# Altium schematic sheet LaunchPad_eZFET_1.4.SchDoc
size 431 x 279 mm; Date: Not shown in title block; ApprovedBy: Not shown in title block; CheckedBy: Not shown in title block; Author: Not shown in title block; CompanyName: Not shown in title block; Engineer: Not shown in title block; Organization: Not shown in title block; Address1: Not shown in title block; Address2: Not shown in title block; Address3: Not shown in title block; Address4: Not shown in title block; DocumentNumber: 1; Revision: Use project parameter SCH_Rev; SheetNumber: 1; SheetTotal: 3; PageSetup: Record=PageOptions¦CenterHorizontal=True¦CenterVertical=True¦PrintScale=1.00¦XCorrection=1.00¦YCorrection=1.00¦PrintKind=0¦BorderSize=5000000¦LeftOffset=0¦BottomOffset=0¦Orientation=2¦PaperLength=1000¦PaperWidth=1000¦Scale=100¦PaperSource=15¦PrintQuality=600¦MediaType=1¦DitherType=10¦PaperKind=Letter¦PrintScaleMode=1
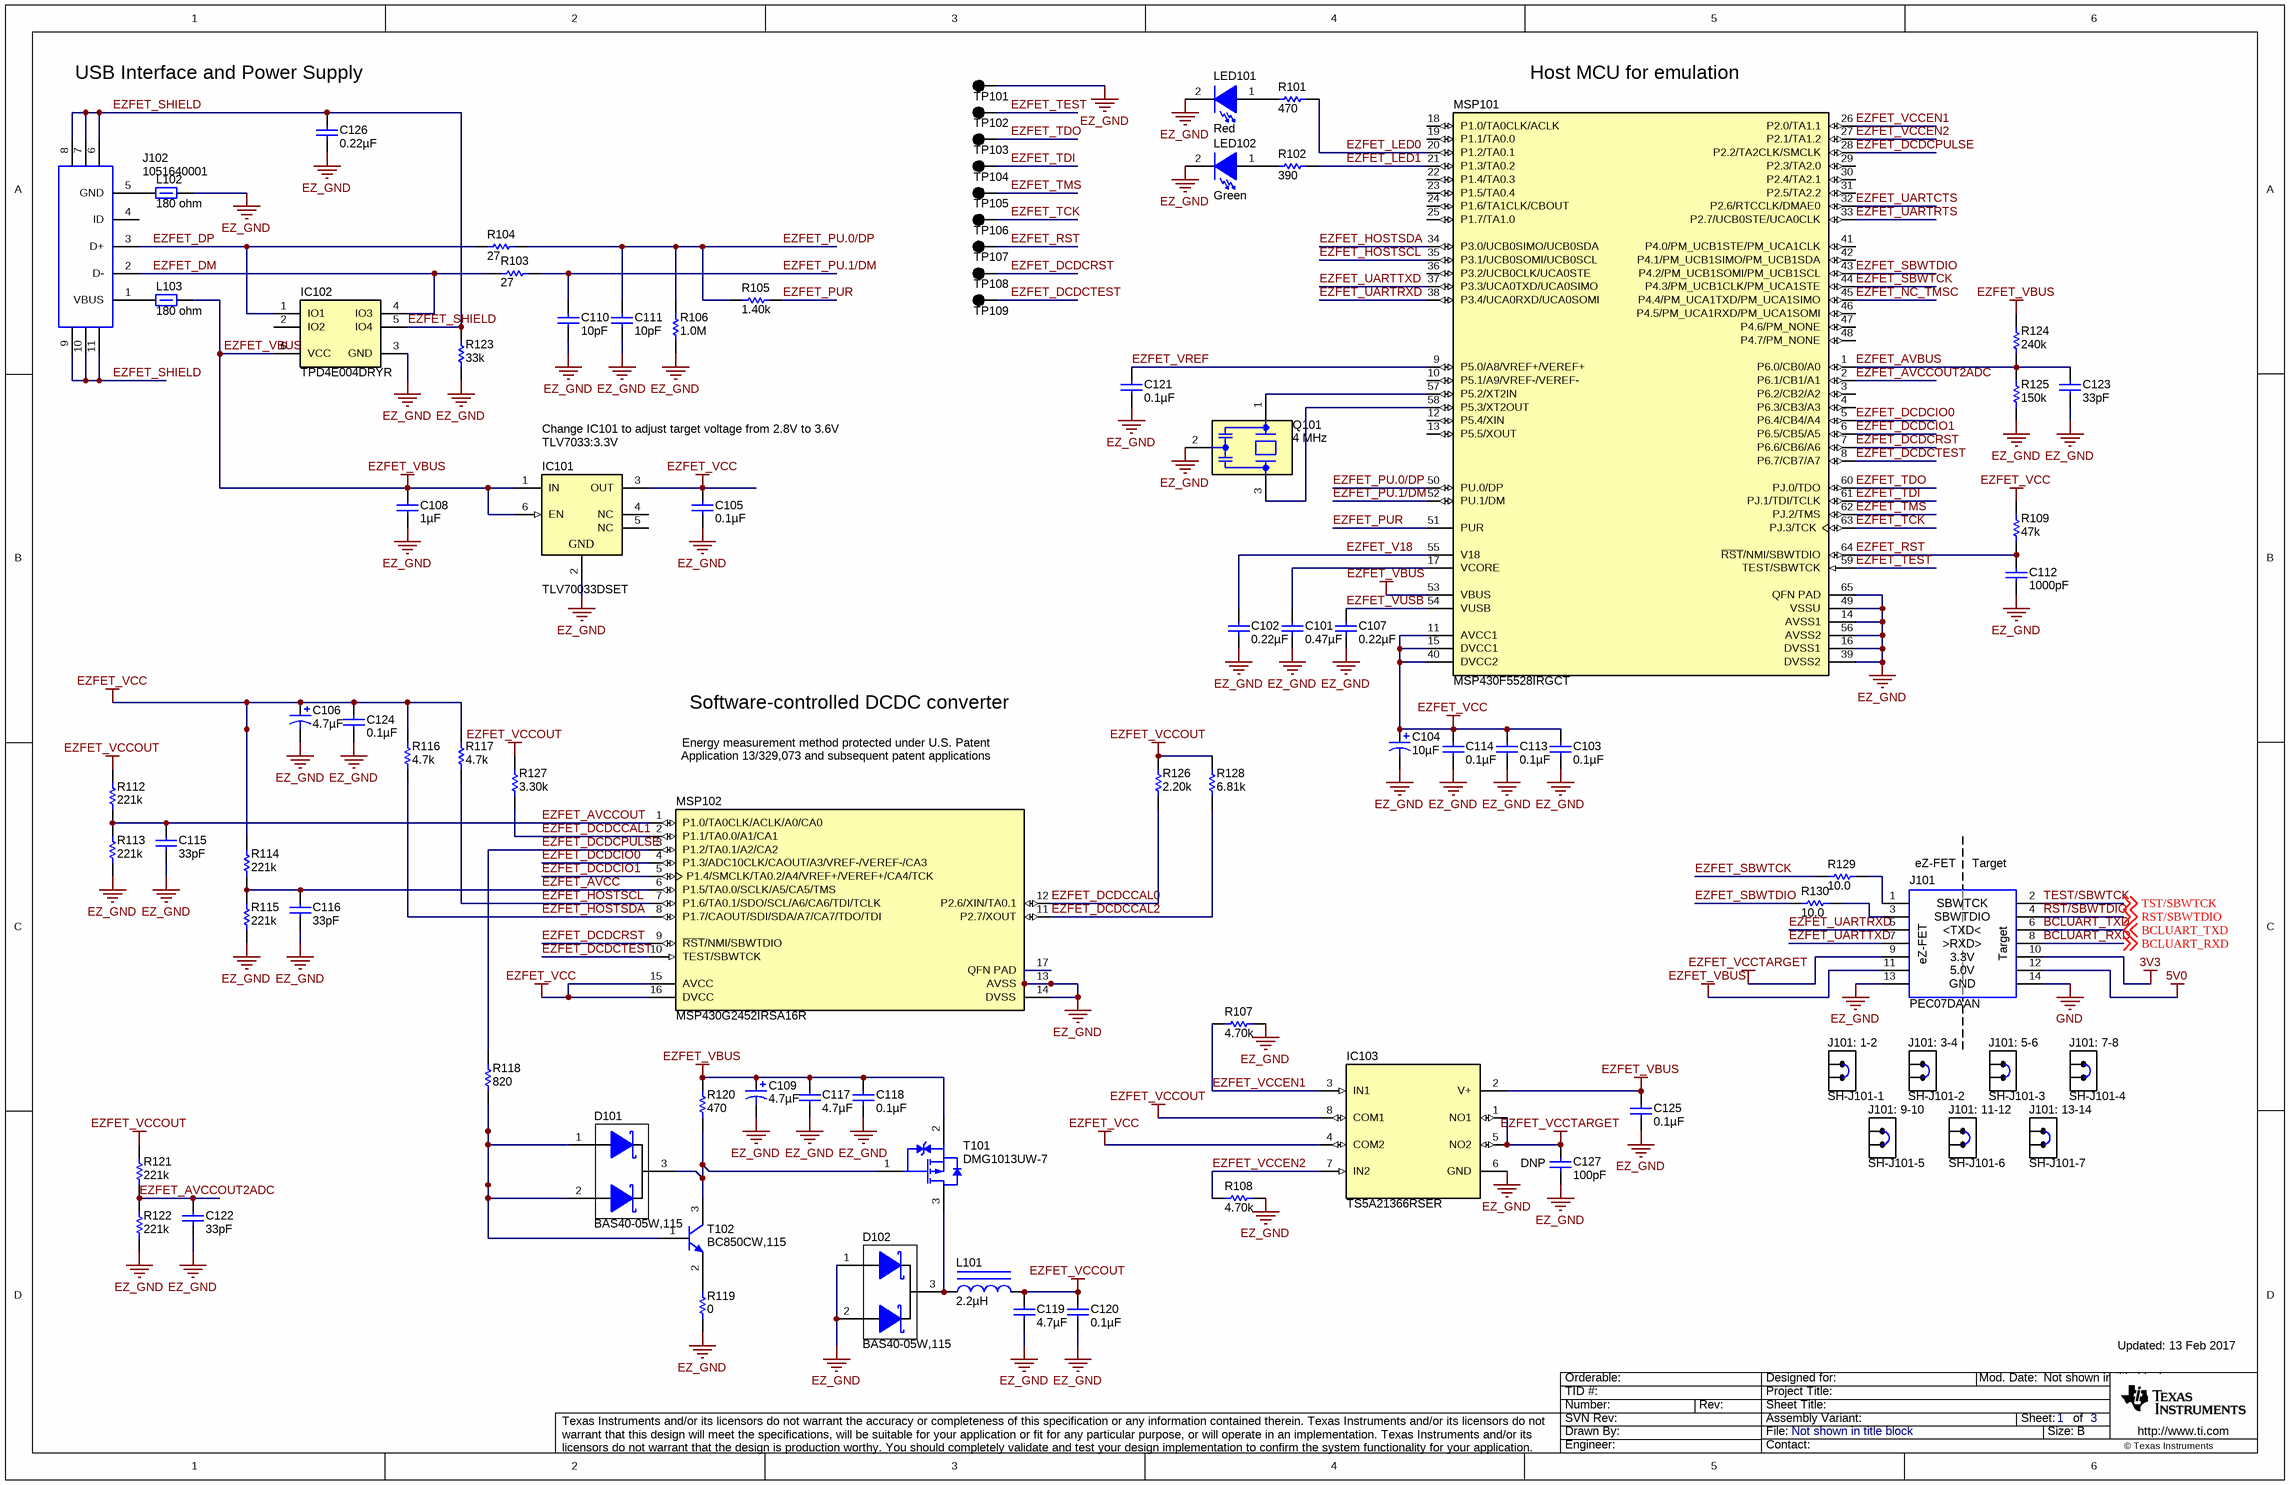
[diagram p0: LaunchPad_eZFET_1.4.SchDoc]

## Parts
C101  ValueDisplayed: 0.47µF  [0402]  (hidden comment: GRM155R61C474KE01)
C102  ValueDisplayed: 0.22µF  [0603]  (hidden comment: GRM188R61C224KA88D)
C103  ValueDisplayed: 0.1µF  [0402]  (hidden comment: GRM155R61A104KA01D)
C104  ValueDisplayed: 10µF  [3216-18]  (hidden comment: 293D106X0010A2TE3)
C105  ValueDisplayed: 0.1µF  [0402]  (hidden comment: GRM155R61A104KA01D)
C106  ValueDisplayed: 4.7µF  [3216-18]  (hidden comment: 293D475X9010A2TE3)
C107  ValueDisplayed: 0.22µF  [0603]  (hidden comment: GRM188R61C224KA88D)
C108  ValueDisplayed: 1µF  [0603]  (hidden comment: GRM185R61A105KE36D)
C109  ValueDisplayed: 4.7µF  [3216-18]  (hidden comment: 293D475X9010A2TE3)
C110  ValueDisplayed: 10pF  [0402]  (hidden comment: GRM1555C1H100JA01D)
C111  ValueDisplayed: 10pF  [0402]  (hidden comment: GRM1555C1H100JA01D)
C112  ValueDisplayed: 1000pF  [0402]  (hidden comment: GRM155R71H102KA01D)
C113  ValueDisplayed: 0.1µF  [0402]  (hidden comment: GRM155R61A104KA01D)
C114  ValueDisplayed: 0.1µF  [0402]  (hidden comment: GRM155R61A104KA01D)
C115  ValueDisplayed: 33pF  [0402]  (hidden comment: GRM1555C1H330JA01D)
C116  ValueDisplayed: 33pF  [0402]  (hidden comment: GRM1555C1H330JA01D)
C117  ValueDisplayed: 4.7µF  [0603]  (hidden comment: GRM188R61C475KAAJ)
C118  ValueDisplayed: 0.1µF  [0402]  (hidden comment: GRM155R61A104KA01D)
C119  ValueDisplayed: 4.7µF  [0603]  (hidden comment: GRM188R61C475KAAJ)
C120  ValueDisplayed: 0.1µF  [0402]  (hidden comment: GRM155R61A104KA01D)
C121  ValueDisplayed: 0.1µF  [0402]  (hidden comment: GRM155R61A104KA01D)
C122  ValueDisplayed: 33pF  [0402]  (hidden comment: GRM1555C1H330JA01D)
C123  ValueDisplayed: 33pF  [0402]  (hidden comment: GRM1555C1H330JA01D)
C124  ValueDisplayed: 0.1µF  [0402]  (hidden comment: GRM155R61A104KA01D)
C125  ValueDisplayed: 0.1µF  [0402]  (hidden comment: GRM155R61A104KA01D)
C126  ValueDisplayed: 0.22µF  [0402]  (hidden comment: GRM155R61A224KE19D)
C127  ValueDisplayed: 100pF  Note: DNP  [0402]  (hidden comment: GRM1555C1H101JA01D)
D101  BAS40-05W,115  [SOT-323]
D102  BAS40-05W,115  [SOT-323]
IC101  TLV70033DSET  [DSE0006A]
IC102  TPD4E004DRYR  [DRY0006A]
IC103  TS5A21366RSER  [RSE0008A]
J101  PEC07DAAN  [PEC07DAAN_Launchpad_EZ-FET]
J102  1051640001  [Molex_1051640001]
L101  ValueDisplayed: 2.2µH  [CBC2518]  (hidden comment: CBC2518T2R2M)
L102  ValueDisplayed: 180 ohm  [0603]  (hidden comment: 742792622)
L103  ValueDisplayed: 180 ohm  [0603]  (hidden comment: 742792622)
LED101  value Red  [LED_LTST-C190_Red]  (hidden comment: LTST-C190CKT)
LED102  value Green  [LED_LTST-C190]  (hidden comment: LTST-C190GKT)
MSP101  MSP430F5528IRGCT  [RGC0064B]
MSP102  MSP430G2452IRSA16R  [RSA0016B]
Q101  Frequency: 4 MHz  [Murata_CSTCR]  (hidden comment: CSTCR4M00G15L99-R0)
R101  ValueDisplayed: 470  [0402]  (hidden comment: CRCW0402470RJNED)
R102  ValueDisplayed: 390  [0402]  (hidden comment: CRCW0402390RJNED)
R103  ValueDisplayed: 27  [0402]  (hidden comment: CRCW040227R0JNED)
R104  ValueDisplayed: 27  [0402]  (hidden comment: CRCW040227R0JNED)
R105  ValueDisplayed: 1.40k  [0402]  (hidden comment: CRCW04021K40FKED)
R106  ValueDisplayed: 1.0M  [0402]  (hidden comment: CRCW04021M00JNED)
R107  ValueDisplayed: 4.70k  [0402]  (hidden comment: CRG0402F4K7)
R108  ValueDisplayed: 4.70k  [0402]  (hidden comment: CRG0402F4K7)
R109  ValueDisplayed: 47k  [0402]  (hidden comment: CRCW040247K0JNED)
R112  ValueDisplayed: 221k  [0402]  (hidden comment: CRCW0402221KFKED)
R113  ValueDisplayed: 221k  [0402]  (hidden comment: CRCW0402221KFKED)
R114  ValueDisplayed: 221k  [0402]  (hidden comment: CRCW0402221KFKED)
R115  ValueDisplayed: 221k  [0402]  (hidden comment: CRCW0402221KFKED)
R116  ValueDisplayed: 4.7k  [0402]  (hidden comment: CRCW04024K70JNED)
R117  ValueDisplayed: 4.7k  [0402]  (hidden comment: CRCW04024K70JNED)
R118  ValueDisplayed: 820  [0402]  (hidden comment: RC0402FR-07820RL)
R119  ValueDisplayed: 0  [0402]  (hidden comment: CRCW04020000Z0ED)
R120  ValueDisplayed: 470  [0402]  (hidden comment: CRCW0402470RJNED)
R121  ValueDisplayed: 221k  [0402]  (hidden comment: CRCW0402221KFKED)
R122  ValueDisplayed: 221k  [0402]  (hidden comment: CRCW0402221KFKED)
R123  ValueDisplayed: 33k  [0402]  (hidden comment: CRCW040233K0JNED)
R124  ValueDisplayed: 240k  [0402]  (hidden comment: CRCW0402240KFKED)
R125  ValueDisplayed: 150k  [0402]  (hidden comment: CRCW0402150KFKED)
R126  ValueDisplayed: 2.20k  [0402]  (hidden comment: CRCW04022K20FKED)
R127  ValueDisplayed: 3.30k  [0402]  (hidden comment: ERJ-2RKF3301X)
R128  ValueDisplayed: 6.81k  [0402]  (hidden comment: CRCW04026K81FKED)
R129  ValueDisplayed: 10.0  [0402]  (hidden comment: CRCW040210R0FKED)
R130  ValueDisplayed: 10.0  [0402]  (hidden comment: CRCW040210R0FKED)
SH-J101-1  Note: J101: 1-2  [SNT-100-BK-G]  (hidden comment: SNT-100-BK-G)
SH-J101-2  Note: J101: 3-4  [SNT-100-BK-G]  (hidden comment: SNT-100-BK-G)
SH-J101-3  Note: J101: 5-6  [SNT-100-BK-G]  (hidden comment: SNT-100-BK-G)
SH-J101-4  Note: J101: 7-8  [SNT-100-BK-G]  (hidden comment: SNT-100-BK-G)
SH-J101-5  Note: J101: 9-10  [SNT-100-BK-G]  (hidden comment: SNT-100-BK-G)
SH-J101-6  Note: J101: 11-12  [SNT-100-BK-G]  (hidden comment: SNT-100-BK-G)
SH-J101-7  Note: J101: 13-14  [SNT-100-BK-G]  (hidden comment: SNT-100-BK-G)
T101  DMG1013UW-7  [SOT-323]
T102  BC850CW,115  [SOT-323]
TP101  5001  [Keystone5001]  (value not drawn)
TP102  5001  [Keystone5001]  (value not drawn)
TP103  5001  [Keystone5001]  (value not drawn)
TP104  5001  [Keystone5001]  (value not drawn)
TP105  5001  [Keystone5001]  (value not drawn)
TP106  5001  [Keystone5001]  (value not drawn)
TP107  5001  [Keystone5001]  (value not drawn)
TP108  5001  [Keystone5001]  (value not drawn)
TP109  5001  [Keystone5001]  (value not drawn)

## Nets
3V3: J101.10
5V0: J101.12
EZ_GND: C101.1 C102.1 C103.1 C104.2(-) C105.1 C106.2(-) C107.1 C108.1 C109.2(-) C110.2 C111.2 C112.1 C113.1 C114.1 C115.1 C116.1 C117.1 C118.1 C119.1 C120.1 C121.1 C122.1 C123.1 C124.1 C125.1 C126.1 C127.2 D102.1(A) D102.2(A) IC101.2(GND) IC102.3(GND) IC103.6(GND) J101.13 L102.2 LED101.2(K) LED102.2(K) MSP101.14(AVSS1) MSP101.16(DVSS1) MSP101.39(DVSS2) MSP101.49(VSSU) MSP101.56(AVSS2) MSP101.65(QFN_PAD) MSP102.13(AVSS) MSP102.14(DVSS) MSP102.17(QFN_PAD) Q101.2(GND) R106.1 R107.1 R108.1 R113.2 R115.2 R119.1 R122.2 R123.1 R125.2 TP101.1
EZFET_VBUS: C108.2 C109.1(+) C117.2 C118.2 C125.2 IC101.1(IN) IC101.6(EN) IC102.6(VCC) IC103.2(V+) J101.11 L103.2 MSP101.53(VBUS) R120.2 R124.1 T101.2(S)
EZFET_VCC: C103.2 C104.1(+) C105.2 C106.1(+) C113.2 C114.2 C124.2 IC101.3(OUT) IC103.4(COM2) MSP101.11(AVCC1) MSP101.15(DVCC1) MSP101.40(DVCC2) MSP102.15(AVCC) MSP102.16(DVCC) R109.1 R114.1 R116.1 R117.1
EZFET_VCCOUT: C119.2 C120.2 IC103.8(COM1) L101.2 R112.1 R121.1 R126.2 R127.2 R128.1
EZFET_VCCTARGET: C127.1 IC103.1(NO1) IC103.5(NO2) J101.9
GND: J101.14
BCLUART_RXD: J101.8 ; off-sheet BCLUART_RXD
BCLUART_TXD: J101.6 ; off-sheet BCLUART_TXD
EZFET_AVBUS: C123.2 MSP101.1(P6.0/CB0/A0) R124.2 R125.1
EZFET_AVCC: C116.2 MSP102.6(P1.5/TA0.0/SCLK/A5/CA5/TMS) R114.2 R115.1
EZFET_AVCCOUT: C115.2 MSP102.1(P1.0/TA0CLK/ACLK/A0/CA0) R112.2 R113.1
EZFET_AVCCOUT2ADC: C122.2 MSP101.2(P6.1/CB1/A1) R121.2 R122.1
EZFET_DCDCCAL0: MSP102.12(P2.6/XIN/TA0.1) R126.1
EZFET_DCDCCAL1: MSP102.2(P1.1/TA0.0/A1/CA1) R127.1
EZFET_DCDCCAL2: MSP102.11(P2.7/XOUT) R128.2
EZFET_DCDCIO0: MSP101.5(P6.4/CB4/A4) MSP102.4(P1.3/ADC10CLK/CAOUT/A3/VREF-/VEREF-/CA3)
EZFET_DCDCIO1: MSP101.6(P6.5/CB5/A5) MSP102.5(P1.4/SMCLK/TA0.2/A4/VREF+/VEREF+/CA4/TCK)
EZFET_DCDCPULSE: MSP101.28(P2.2/TA2CLK/SMCLK) MSP102.3(P1.2/TA0.1/A2/CA2) R118.2
EZFET_DCDCRST: MSP101.7(P6.6/CB6/A6) MSP102.9(~{RST}/NMI/SBWTDIO) TP108.1
EZFET_DCDCTEST: MSP101.8(P6.7/CB7/A7) MSP102.10(TEST/SBWTCK) TP109.1
EZFET_DM: IC102.4(IO3) J102.2(D-) R103.1
EZFET_DP: IC102.1(IO1) J102.3(D+) R104.1
EZFET_HOSTSCL: MSP101.35(P3.1/UCB0SOMI/UCB0SCL) MSP102.7(P1.6/TA0.1/SDO/SCL/A6/CA6/TDI/TCLK) R117.2
EZFET_HOSTSDA: MSP101.34(P3.0/UCB0SIMO/UCB0SDA) MSP102.8(P1.7/CAOUT/SDI/SDA/A7/CA7/TDO/TDI) R116.2
EZFET_LED0: MSP101.20(P1.2/TA0.1) R101.2
EZFET_LED1: MSP101.21(P1.3/TA0.2) R102.2
EZFET_NC_TMSC: MSP101.45(P4.4/PM_UCA1TXD/PM_UCA1SIMO)
EZFET_PU.0/DP: C111.1 MSP101.50(PU.0/DP) R104.2 R105.2 R106.2
EZFET_PU.1/DM: C110.1 MSP101.52(PU.1/DM) R103.2
EZFET_PUR: MSP101.51(PUR) R105.1
EZFET_RST: C112.2 MSP101.64(~{RST}/NMI/SBWTDIO) R109.2 TP107.1
EZFET_SBWTCK: MSP101.44(P4.3/PM_UCB1CLK/PM_UCA1STE) R129.1
EZFET_SBWTDIO: MSP101.43(P4.2/PM_UCB1SOMI/PM_UCB1SCL) R130.1
EZFET_SHIELD: C126.2 IC102.5(IO4) J102.6 J102.7 J102.8 J102.9 J102.10 J102.11 R123.2
EZFET_TCK: MSP101.63(PJ.3/TCK) TP106.1
EZFET_TDI: MSP101.61(PJ.1/TDI/TCLK) TP104.1
EZFET_TDO: MSP101.60(PJ.0/TDO) TP103.1
EZFET_TEST: MSP101.59(TEST/SBWTCK) TP102.1
EZFET_TMS: MSP101.62(PJ.2/TMS) TP105.1
EZFET_UARTCTS: MSP101.32(P2.6/RTCCLK/DMAE0)
EZFET_UARTRTS: MSP101.33(P2.7/UCB0STE/UCA0CLK)
EZFET_UARTRXD: J101.5 MSP101.38(P3.4/UCA0RXD/UCA0SOMI)
EZFET_UARTTXD: J101.7 MSP101.37(P3.3/UCA0TXD/UCA0SIMO)
EZFET_V18: C102.2 MSP101.55(V18)
EZFET_VCCEN1: IC103.3(IN1) MSP101.26(P2.0/TA1.1) R107.2
EZFET_VCCEN2: IC103.7(IN2) MSP101.27(P2.1/TA1.2) R108.2
EZFET_VREF: C121.2 MSP101.9(P5.0/A8/VREF+/VEREF+)
EZFET_VUSB: C107.2 MSP101.54(VUSB)
~{RST}/SBWTDIO: J101.4 ; off-sheet RST/SBWTDIO  [also labelled RST/SBWTDIO]
TEST/SBWTCK: J101.2 ; off-sheet TST/SBWTCK  [also labelled TST/SBWTCK]
NetC101_2: C101.2 MSP101.17(VCORE)
NetD101_1: D101.1(A) D101.2(A) R118.1 T102.1(B)
NetD101_3: D101.3(K) R120.1 T101.1(G) T102.3(C)
NetD102_3: D102.3(K) L101.1 T101.3(D)
NetJ101_1: J101.1 R129.2
NetJ101_3: J101.3 R130.2
NetJ102_1: J102.1(VBUS) L103.1
NetJ102_5: J102.5(GND) L102.1
NetLED101_1: LED101.1(A) R101.1
NetLED102_1: LED102.1(A) R102.1
NetMSP101_57: MSP101.57(P5.2/XT2IN) Q101.1(In)
NetMSP101_58: MSP101.58(P5.3/XT2OUT) Q101.3(Out)
NetR119_2: R119.2 T102.2(E)

Not connected (* = marked no-connect by the designer): IC101 4(NC) 5(NC); IC102 2(IO2); J102 4(ID); MSP101 3(P6.2/CB2/A2) 4(P6.3/CB3/A3) 10(P5.1/A9/VREF-/VEREF-) 12(P5.4/XIN) 13(P5.5/XOUT) 18(P1.0/TA0CLK/ACLK) 19(P1.1/TA0.0) 22(P1.4/TA0.3) 23(P1.5/TA0.4) 24(P1.6/TA1CLK/CBOUT) 25(P1.7/TA1.0) 29(P2.3/TA2.0) 30(P2.4/TA2.1) 31(P2.5/TA2.2) 36(P3.2/UCB0CLK/UCA0STE) 41(P4.0/PM_UCB1STE/PM_UCA1CLK) 42(P4.1/PM_UCB1SIMO/PM_UCB1SDA) 46(P4.5/PM_UCA1RXD/PM_UCA1SOMI) 47(P4.6/PM_NONE) 48(P4.7/PM_NONE)

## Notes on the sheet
- (near C126) USB Interface and Power Supply
- (near MSP101) Host MCU for emulation
- Change IC101 to adjust target voltage from 2.8V to 3.6V
- (near IC101) TLV7033:3.3V
- Software-controlled DCDC converter
- Energy measurement method protected under U.S. Patent
- Application 13/329,073 and subsequent patent applications
- (near J101) eZ-FET
- (near J101) Target
- Updated: 13 Feb 2017

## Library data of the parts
C101 = GRM155R61C474KE01: CAP, CERM, 0.47 µF, 16 V, +/- 10%, X5R, 0402; Manufacturer: MuRata; Polarized: N; CompType: Capacitor; Value: 0.47uF; U/M: EA; Cap_F: 0.00000047; Tolerance_%: 10; Value1: Unknown; VDC_V: 16; Value2: 16V; TaMin_C: -55; TaMax_C: 85; SizeArea_mm2: 0.5; SizeAreaWB_mm2: 3; SizeX_mm: 1; SizeZ_mm: 0.6; AEC Category: Q200
C102 C107 = GRM188R61C224KA88D: CAP, CERM, 0.22 µF, 16 V, +/- 10%, X5R, 0603; Manufacturer: MuRata; Polarized: N; CompType: Capacitor; Value: 0.22uF; U/M: EA; Cap_F: 0.00000022; Tolerance_%: 10; Value1: Unknown; VDC_V: 16; Value2: 16V; TaMin_C: -55; TaMax_C: 85; SizeArea_mm2: 1.28; SizeAreaWB_mm2: 4.68; SizeX_mm: 1.6; SizeY_mm: 0.8; SizeZ_mm: 1; AEC Category: Q200
C103 C105 C113 C114 C118 C120 C121 C124 C125 = GRM155R61A104KA01D: CAP, CERM, 0.1 µF, 10 V, +/- 10%, X5R, 0402; Manufacturer: MuRata; Polarized: N; CompType: Capacitor; Value: 0.1uF; U/M: EA; Cap_F: 0.0000001; Tolerance_%: 10; Value1: Unknown; Value2: 10V; TaMin_C: -55; TaMax_C: 85; SizeArea_mm2: 0.5; SizeAreaWB_mm2: 3; SizeX_mm: 1; SizeZ_mm: 0.6; AEC Category: Q200
C104 = 293D106X0010A2TE3: CAP, TA, 10 µF, 10 V, +/- 20%, 3.4 ohm, SMD; Manufacturer: Vishay-Sprague; Polarized: Y; CompType: Capacitor; Value: 10uF; U/M: EA; Cap_F: 0.00001; Tolerance_%: 20; Value1: 3.4 ohm; VDC_V: 10; Value2: 10V; ESR_ohm: 3.4; IRMS_A: 0.15; TaMin_C: -55; TaMax_C: 125; Cap_Case: A; SizeAreaWB_mm2: 10.92; SizeArea_mm2: 5.12; SizeX_mm: 3.2; SizeY_mm: 1.6; SizeZ_mm: 1.8; AEC Category: Q200
C106 C109 = 293D475X9010A2TE3: CAP, TA, 4.7 µF, 10 V, +/- 10%, 5 ohm, SMD; Manufacturer: Vishay-Sprague; Polarized: Y; CompType: Capacitor; Value: 4.7uF; U/M: EA; Cap_F: 0.0000047; Tolerance_%: 10; Value1: 5 ohm; Value2: 10V; ESR_ohm: 5; IRMS_A: 0.12; TaMin_C: -55; TaMax_C: 125; Cap_Case: A; SizeAreaWB_mm2: 10.92; SizeArea_mm2: 5.12; SizeX_mm: 3.2; SizeY_mm: 1.6; SizeZ_mm: 1.8; AEC Category: Q200
C108 = GRM185R61A105KE36D: CAP, CERM, 1 µF, 10 V, +/- 10%, X5R, 0603; Manufacturer: MuRata; Polarized: N; CompType: Capacitor; Value: 1uF; U/M: EA; Cap_F: 0.000001; Tolerance_%: 10; Value1: Unknown; Value2: 10V; TaMin_C: -55; TaMax_C: 85; SizeArea_mm2: 1.28; SizeAreaWB_mm2: 4.68; SizeX_mm: 1.6; SizeY_mm: 0.8; SizeZ_mm: 1; AEC Category: Q200
C110 C111 = GRM1555C1H100JA01D: CAP, CERM, 10 pF, 50 V, +/- 5%, C0G/NP0, 0402; Manufacturer: MuRata; Polarized: N; CompType: Capacitor; Value: 10pF; U/M: EA; Cap_F: 0.00000000001; Tolerance_%: 5; Value1: Unknown; VDC_V: 50; Value2: 50V; TaMin_C: -55; TaMax_C: 125; SizeArea_mm2: 0.5; SizeAreaWB_mm2: 3; SizeX_mm: 1; SizeZ_mm: 0.6; AEC Category: Q200
C112 = GRM155R71H102KA01D: CAP, CERM, 1000 pF, 50 V, +/- 10%, X7R, 0402; Manufacturer: MuRata; Polarized: N; CompType: Capacitor; Value: 1000pF; U/M: EA; Cap_F: 0.000000001; Tolerance_%: 10; Value1: Unknown; VDC_V: 50; Value2: 50V; TaMin_C: -55; TaMax_C: 125; SizeArea_mm2: 0.5; SizeAreaWB_mm2: 3; SizeX_mm: 1; SizeZ_mm: 0.6; AEC Category: Q200
C115 C116 C122 C123 = GRM1555C1H330JA01D: CAP, CERM, 33 pF, 50 V, +/- 5%, C0G/NP0, 0402; Manufacturer: MuRata; Polarized: N; CompType: Capacitor; Value: 33pF; U/M: EA; Cap_F: 0.000000000033; Tolerance_%: 5; Value1: Unknown; VDC_V: 50; Value2: 50V; TaMin_C: -55; TaMax_C: 125; SizeArea_mm2: 0.5; SizeAreaWB_mm2: 3; SizeX_mm: 1; SizeZ_mm: 0.6; AEC Category: Q200
C117 C119 = GRM188R61C475KAAJ: CAP, CERM, 4.7 µF, 16 V, +/- 10%, X5R, 0603; Manufacturer: MuRata; Polarized: N; CompType: Capacitor; Value: 4.7uF; U/M: EA; Cap_F: 0.0000047; Tolerance_%: 10; Value1: Unknown; VDC_V: 16; Value2: 16V; TaMin_C: -55; TaMax_C: 85; SizeArea_mm2: 1.28; SizeAreaWB_mm2: 4.68; SizeX_mm: 1.6; SizeY_mm: 0.8; SizeZ_mm: 1; AEC Category: Q200; Note: Use Exact Part
C126 = GRM155R61A224KE19D: CAP, CERM, 0.22 µF, 10 V, +/- 10%, X5R, 0402; Manufacturer: MuRata; Polarized: N; CompType: Capacitor; Value: 0.22uF; U/M: EA; Cap_F: 0.00000022; Tolerance_%: 10; Value1: Unknown; Value2: 10V; TaMin_C: -55; TaMax_C: 85; SizeArea_mm2: 0.5; SizeAreaWB_mm2: 3; SizeX_mm: 1; SizeZ_mm: 0.6; AEC Category: Q200
C127 = GRM1555C1H101JA01D: CAP, CERM, 100 pF, 50 V, +/- 5%, C0G/NP0, 0402; Manufacturer: MuRata; Polarized: N; CompType: Capacitor; Value: 100pF; U/M: EA; Cap_F: 0.0000000001; Tolerance_%: 5; Value1: Unknown; VDC_V: 50; Value2: 50V; TaMin_C: -55; TaMax_C: 125; SizeArea_mm2: 0.5; SizeAreaWB_mm2: 3; SizeX_mm: 1; SizeZ_mm: 0.6; AEC Category: Q200
D101 D102 = BAS40-05W,115: Diode, Schottky, 40 V, 0.12 A, AEC-Q101, SOT-323; Manufacturer: NXP Semiconductor; SymbolCreator: a0412235; U/M: EA; Vf_V: 1; Value: 40V; Value1: 0.12A; Value2: 1V; Io_A: 0.12; Vr_V: 40; TJmax_C: 150; SizeAreaWB_mm2: 10.24; SizeArea_mm2: 4.84; SizeX_mm: 2.2; SizeZ_mm: 1.1; AEC Category: Q101; AEC Qualified: Y; Note: Use Exact Part
IC101 = TLV70033DSET: Single Output LDO, 200 mA, Fixed 3.3 V Output, 2 to 5.5 V Input, with Low IQ, 6-pin WSON (DSE), -40 to 125 degC, Green (RoHS & no Sb/Br); Manufacturer: Texas Instruments; Alternate PartNumber: Equivalent; Accuracy(%): 2; Fixed Output Options(V): 3.3; Iout(Max)(A): 0.2; Iq(Typ)(mA): 0.03; SubFamily: Single Channel LDO; Vdo(Typ)(mV): 175; Vin(Max)(V): 5.5; Note: TI Provided
IC102 = TPD4E004DRYR: ESD-Protection Array for High-Speed Data Interfaces, 4 Channels, -40 to +85 degC, 6-pin SON (DRY), Green (RoHS & no Sb/Br); Manufacturer: Texas Instruments; Alternate PartNumber: Equivalent; 1394 / Firewire: TRUE; Breakdown Voltage(Min)(V): 6; IEC 61000-4-2 Air-Gap(+/- kV): 12; IEC 61000-4-2 Contact(+/- kV): 8; IO Capacitance(Typ)(pF): 1.6; IO Leakage Current(nA): 1; SubFamily: ESD Solution; Note: TI Provided
IC103 = TS5A21366RSER: 0.75-Ohm DUAL SPST ANALOG SWITCH WITH 1.8-V COMPATIBLE INPUT LOGIC, RSE0008A (UQFN-8); Manufacturer: Texas Instruments; SymbolCreator: a0411947; SizeArea_mm2: 2.25; SizeAreaWB_mm2: 6.25; SizeX_mm: 1.5; SizeZ_mm: 0.6; CompType: IC; U/M: EA; Note: TI Provided
J101 = PEC07DAAN: Header, 100mil, 7x2, Tin, TH; Manufacturer: Sullins Connector Solutions; SymbolCreator: a0412235; Pitch_mm: 2.54; Gender: Male; Shrouded: N; Row_Count: 2; Current_A: 3; Voltage_V: 1800; Cert_UL: Y
J102 = 1051640001: Receptacle, USB 2.0, Micro B, 5 Position, R/A, SMT; Manufacturer: Molex; SymbolCreator: a0411947; Pitch_mm: 0.65; Gender: Female; ContactFinish: Gold; Current_A: 1.8; Voltage_V: 30; Cert_UL: Y; Note: Use Exact Part
L101 = CBC2518T2R2M: Inductor, Wirewound, Ceramic, 2.2 µH, 0.89 A, 0.13 ohm, SMD; Manufacturer: Taiyo Yuden; Value: 2.2uH; Ind_H: 2.2E-6; Imax_A: 0.89; Irms: 1.1A @ 40C rise; Isat: 0.89A @ 30% inductance drop; DCR_ohm: 0.13; Value2: 0.89A; SizeAreaWB_mm2: 9.8; SizeArea_mm2: 4.5; SizeX_mm: 2.5; SizeY_mm: 1.8; AEC Category: Q200; AEC Qualified: N; Note: Use Exact Part
L102 L103 = 742792622: Ferrite Bead, 180 ohm @ 100 MHz, 0.5 A, 0603; Manufacturer: Wurth Elektronik; Value: 180 ohm; Imax_A: 0.5; DCR_ohm: 0.3; Value1: 0.3 ohm; Value2: 0.5A; SizeAreaWB_mm2: 4.68; SizeArea_mm2: 1.28; SizeX_mm: 1.6; SizeY_mm: 0.8; SizeZ_mm: 1; ZTyp@100MHz_Ohm: 180; Ztyp@1GHz_Ohm: 190.577
LED101 = LTST-C190CKT: LED, Red, SMD; Manufacturer: Lite-On; Vf_V: 2; Value2: 2V; Io_A: 0.02; Tjmax_C: 85; Power_TotalModule: 0.0625; Value1: 0.0625W; U/M: EA
LED102 = LTST-C190GKT: LED, Green, SMD; Manufacturer: Lite-On; Vf_V: 2.1; Value2: 2.1V; Io_A: 0.02; Power_TotalModule: 0.1; Value1: 0.1W; U/M: EA
MSP101 = MSP430F5528IRGCT: 25 MHz Mixed Signal Microcontroller with 128 KB Flash, 8192 B SRAM and 47 GPIOs, -40 to 85 degC, 64-pin QFN (RGC), Green (RoHS & no Sb/Br); Alternate Manufacturer: Texas Instruments; Alternate PartNumber: Equivalent; ADC: 12-bit SAR; ADC Channels: 16; Brown Out Reset: Yes; DMA: 3; Flash(KB): 128; Frequency(MHz): 25; GPIO: 47; Multiplier: 32x32; Pin/Package: 64DSBGA, 64VQFN, 80BGA MICROSTAR JUNIOR; SRAM(B): 8192; SubFamily: 5 Series; Timers - 16-bit: 4; USB: 1; USCI_A (UART/LIN/IrDA/SPI): 2; Note: TI Provided
MSP102 = MSP430G2452IRSA16R: 16 MHz Mixed Signal Microcontroller with 8 KB Flash, 256 B SRAM and 16 GPIOs, 16-pin QFN (RSA), Green (RoHS & no Sb/Br); Alternate Manufacturer: Texas Instruments; Alternate PartNumber: Equivalent; ADC: 10-bit SAR; ADC Channels: 8; Brown Out Reset: Yes; Frequency(MHz): 16; Pin/Package: 14TSSOP, 16QFN, 20PDIP, 20TSSOP; SRAM(B): 256; SubFamily: Value Line; Timers - 16-bit: 1; USI: (I2C/SPI); Note: TI Provided
Q101 = CSTCR4M00G15L99-R0: Resonator, 4MHz, 39pF SMD; Manufacturer: MuRata; SymbolCreator: a0799721; U/M: EA; TaMin_C: 0; TaMax_C: 70; Frequency Stability: ±0.08 %; Note: Use Exact Part
R101 R120 = CRCW0402470RJNED: RES, 470, 5%, 0.063 W, 0402; Manufacturer: Vishay-Dale; CompType: Resistor; Value: 470; Value_Code: 470R; Tolerance_%: 5; Power_W: 0.063; Value2: 0.063W; VDC_V: 50; TempCo: 200 ppm/C; SizeArea_mm2: 0.5; SizeX_mm: 1; SizeZ_mm: 0.6; EIA_Code: E24; U/M: EA; AEC Category: Q200
R102 = CRCW0402390RJNED: RES, 390, 5%, 0.063 W, 0402; Manufacturer: Vishay-Dale; CompType: Resistor; Value: 390; Value_Code: 390R; Tolerance_%: 5; Power_W: 0.063; Value2: 0.063W; VDC_V: 50; TempCo: 200 ppm/C; SizeArea_mm2: 0.5; SizeX_mm: 1; SizeZ_mm: 0.6; EIA_Code: E24; U/M: EA; AEC Category: Q200
R103 R104 = CRCW040227R0JNED: RES, 27, 5%, 0.063 W, 0402; Manufacturer: Vishay-Dale; CompType: Resistor; Value: 27; Value_Code: 27R0; Tolerance_%: 5; Power_W: 0.063; Value2: 0.063W; VDC_V: 50; TempCo: 200 ppm/C; SizeArea_mm2: 0.5; SizeX_mm: 1; SizeZ_mm: 0.6; EIA_Code: E24; U/M: EA; AEC Category: Q200
R105 = CRCW04021K40FKED: RES, 1.40 k, 1%, 0.063 W, 0402; Manufacturer: Vishay-Dale; CompType: Resistor; Value: 1.40k; Res_ohm: 1400; Value_Code: 1k40; Tolerance_%: 1; Power_W: 0.063; Value2: 0.063W; VDC_V: 50; TempCo: 100 ppm/C; SizeArea_mm2: 0.5; SizeZ_mm: 0.6; EIA_Code: E96; U/M: EA; AEC Category: Q200
R106 = CRCW04021M00JNED: RES, 1.0 M, 5%, 0.063 W, 0402; Manufacturer: Vishay-Dale; CompType: Resistor; Value: 1.0Meg; Res_ohm: 1000000; Value_Code: 1M00; Tolerance_%: 5; Power_W: 0.063; Value2: 0.063W; VDC_V: 50; TempCo: 200 ppm/C; SizeArea_mm2: 0.5; SizeX_mm: 1; SizeZ_mm: 0.6; EIA_Code: E24; U/M: EA; AEC Category: Q200
R107 R108 = CRG0402F4K7: RES, 4.70 k, 1%, 0.063 W, 0402; Manufacturer: TE Connectivity; CompType: Resistor; Value: 4.70k; Res_ohm: 4700; Value_Code: 4k70; Tolerance_%: 1; Power_W: 0.063; Value2: 0.063W; TempCo: 100 ppm/C; SizeArea_mm2: 0.5; SizeZ_mm: 0.6; U/M: EA; AEC Category: Q200; AEC Qualified: N
R109 = CRCW040247K0JNED: RES, 47 k, 5%, 0.063 W, 0402; Manufacturer: Vishay-Dale; CompType: Resistor; Value: 47k; Res_ohm: 47000; Value_Code: 47k0; Tolerance_%: 5; Power_W: 0.063; Value2: 0.063W; VDC_V: 50; TempCo: 200 ppm/C; SizeArea_mm2: 0.5; SizeX_mm: 1; SizeZ_mm: 0.6; EIA_Code: E24; U/M: EA; AEC Category: Q200
R112-R115 R121 R122 = CRCW0402221KFKED: RES, 221 k, 1%, 0.063 W, 0402; Manufacturer: Vishay-Dale; CompType: Resistor; Value: 221k; Res_ohm: 221000; Tolerance_%: 1; Power_W: 0.063; Value2: 0.063W; VDC_V: 50; TempCo: 100 ppm/C; SizeArea_mm2: 0.5; SizeZ_mm: 0.6; EIA_Code: E96; U/M: EA; AEC Category: Q200
R116 R117 = CRCW04024K70JNED: RES, 4.7 k, 5%, 0.063 W, 0402; Manufacturer: Vishay-Dale; CompType: Resistor; Value: 4.7k; Res_ohm: 4700; Value_Code: 4k70; Tolerance_%: 5; Power_W: 0.063; Value2: 0.063W; VDC_V: 50; TempCo: 200 ppm/C; SizeArea_mm2: 0.5; SizeX_mm: 1; SizeZ_mm: 0.6; EIA_Code: E24; U/M: EA; AEC Category: Q200
R118 = RC0402FR-07820RL: RES, 820, 1%, 0.063 W, 0402; Manufacturer: Yageo America; CompType: Resistor; Value: 820; Value_Code: 820R; Tolerance_%: 1; Power_W: 0.063; Value2: 0.063W; VDC_V: 50; TempCo: 100 ppm/C; SizeArea_mm2: 0.5; SizeZ_mm: 0.6; U/M: EA; AEC Category: Q200; AEC Qualified: N
R119 = CRCW04020000Z0ED: RES, 0, 5%, 0.063 W, 0402; Manufacturer: Vishay-Dale; CompType: Resistor; Value: 0; Value_Code: 0000; Tolerance_%: 5; Power_W: 0.063; Value2: 0.063W; VDC_V: 50; TempCo: 200 ppm/C; SizeArea_mm2: 0.5; SizeX_mm: 1; SizeZ_mm: 0.6; EIA_Code: E24; U/M: EA; AEC Category: Q200
R123 = CRCW040233K0JNED: RES, 33 k, 5%, 0.063 W, 0402; Manufacturer: Vishay-Dale; CompType: Resistor; Value: 33k; Res_ohm: 33000; Value_Code: 33k0; Tolerance_%: 5; Power_W: 0.063; Value2: 0.063W; VDC_V: 50; TempCo: 200 ppm/C; SizeArea_mm2: 0.5; SizeX_mm: 1; SizeZ_mm: 0.6; EIA_Code: E24; U/M: EA; AEC Category: Q200
R124 = CRCW0402240KFKED: RES, 240 k, 1%, 0.063 W, 0402; Manufacturer: Vishay-Dale; CompType: Resistor; Value: 240k; Res_ohm: 240000; Tolerance_%: 1; Power_W: 0.063; Value2: 0.063W; VDC_V: 50; TempCo: 100 ppm/C; SizeArea_mm2: 0.5; SizeZ_mm: 0.6; U/M: EA; AEC Category: Q200
R125 = CRCW0402150KFKED: RES, 150 k, 1%, 0.063 W, 0402; Manufacturer: Vishay-Dale; CompType: Resistor; Value: 150k; Res_ohm: 150000; Tolerance_%: 1; Power_W: 0.063; Value2: 0.063W; VDC_V: 50; TempCo: 100 ppm/C; SizeArea_mm2: 0.5; SizeZ_mm: 0.6; EIA_Code: E96; U/M: EA; AEC Category: Q200
R126 = CRCW04022K20FKED: RES, 2.20 k, 1%, 0.063 W, 0402; Manufacturer: Vishay-Dale; CompType: Resistor; Value: 2.20k; Res_ohm: 2200; Value_Code: 2k20; Tolerance_%: 1; Power_W: 0.063; Value2: 0.063W; TempCo: 100 ppm/C; SizeArea_mm2: 0.5; SizeZ_mm: 0.6; U/M: EA; AEC Category: Q200
R127 = ERJ-2RKF3301X: RES, 3.30 k, 1%, 0.1 W, AEC-Q200 Grade 0, 0402; Manufacturer: Panasonic; CompType: Resistor; Value: 3.30k; Res_ohm: 3300; Value_Code: 3k30; Tolerance_%: 1; Power_W: 0.1; Value2: 0.1W; VDC_V: 50; TempCo: 100 ppm/C; SizeArea_mm2: 0.5; SizeZ_mm: 0.6; U/M: EA; AEC Category: Q200; AEC Qualified: Y; AEC Grade: 0
R128 = CRCW04026K81FKED: RES, 6.81 k, 1%, 0.063 W, 0402; Manufacturer: Vishay-Dale; CompType: Resistor; Value: 6.81k; Res_ohm: 6810; Value_Code: 6k81; Tolerance_%: 1; Power_W: 0.063; Value2: 0.063W; VDC_V: 50; TempCo: 100 ppm/C; SizeArea_mm2: 0.5; SizeZ_mm: 0.6; EIA_Code: E96; U/M: EA; AEC Category: Q200
R129 R130 = CRCW040210R0FKED: RES, 10.0, 1%, 0.063 W, 0402; Manufacturer: Vishay-Dale; CompType: Resistor; Value: 10.0; Res_ohm: 10; Value_Code: 10R0; Tolerance_%: 1; Power_W: 0.063; Value2: 0.063W; VDC_V: 50; TempCo: 100 ppm/C; SizeArea_mm2: 0.5; SizeZ_mm: 0.6; EIA_Code: E96; U/M: EA; AEC Category: Q200
SH-J101-1-SH-J101-7 = SNT-100-BK-G: Shunt, 100mil, Gold plated, Black; Manufacturer: Samtec; Alternate Manufacturer: 3M; Alternate PartNumber: 969102-0000-DA; Value: 1x2
T101 = DMG1013UW-7: MOSFET, P-CH, -20 V, -0.82 A, SOT-323; Manufacturer: Diodes Inc.; Alternate Manufacturer: None; SymbolCreator: a0411947; U/M: EA; ChType: P; Value: -20V; Value1: 0.75 ohm; Rdson45_ohm: 0.75; Value2: 0.622 nC; QgTyp_nC: 0.622; Vgs_V: -6; SizeAreaWB_mm2: 10.24; SizeArea_mm2: 4.84; SizeX_mm: 2.2; SizeZ_mm: 1.1; AEC Category: Q101; Note: Use Exact Part
T102 = BC850CW,115, NXP Semiconductor: Transistor, NPN, 45 V, 0.1 A, SOT-323; CompType: BJT; PNP: 0; NPN: 1; Vceo_V: 45; Vcesat1_V: 0.25; Value: 45 V; IcRated_A: 0.1; Value1: 0.1 A; HfeMax: 800; TaMin_C: -65; TaMax_C: 150; SizeAreaWB_mm2: 10.24; SizeArea_mm2: 4.84; SizeX_mm: 2.2; SizeZ_mm: 1.1; U/M: EA; AEC Category: Q101; Note: Use Exact Part
TP101-TP109 = 5001: Test Point, Miniature, Black, TH; Manufacturer: Keystone; CompType: Test Point Loop; ContactFinish: Silver; Note: DNP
